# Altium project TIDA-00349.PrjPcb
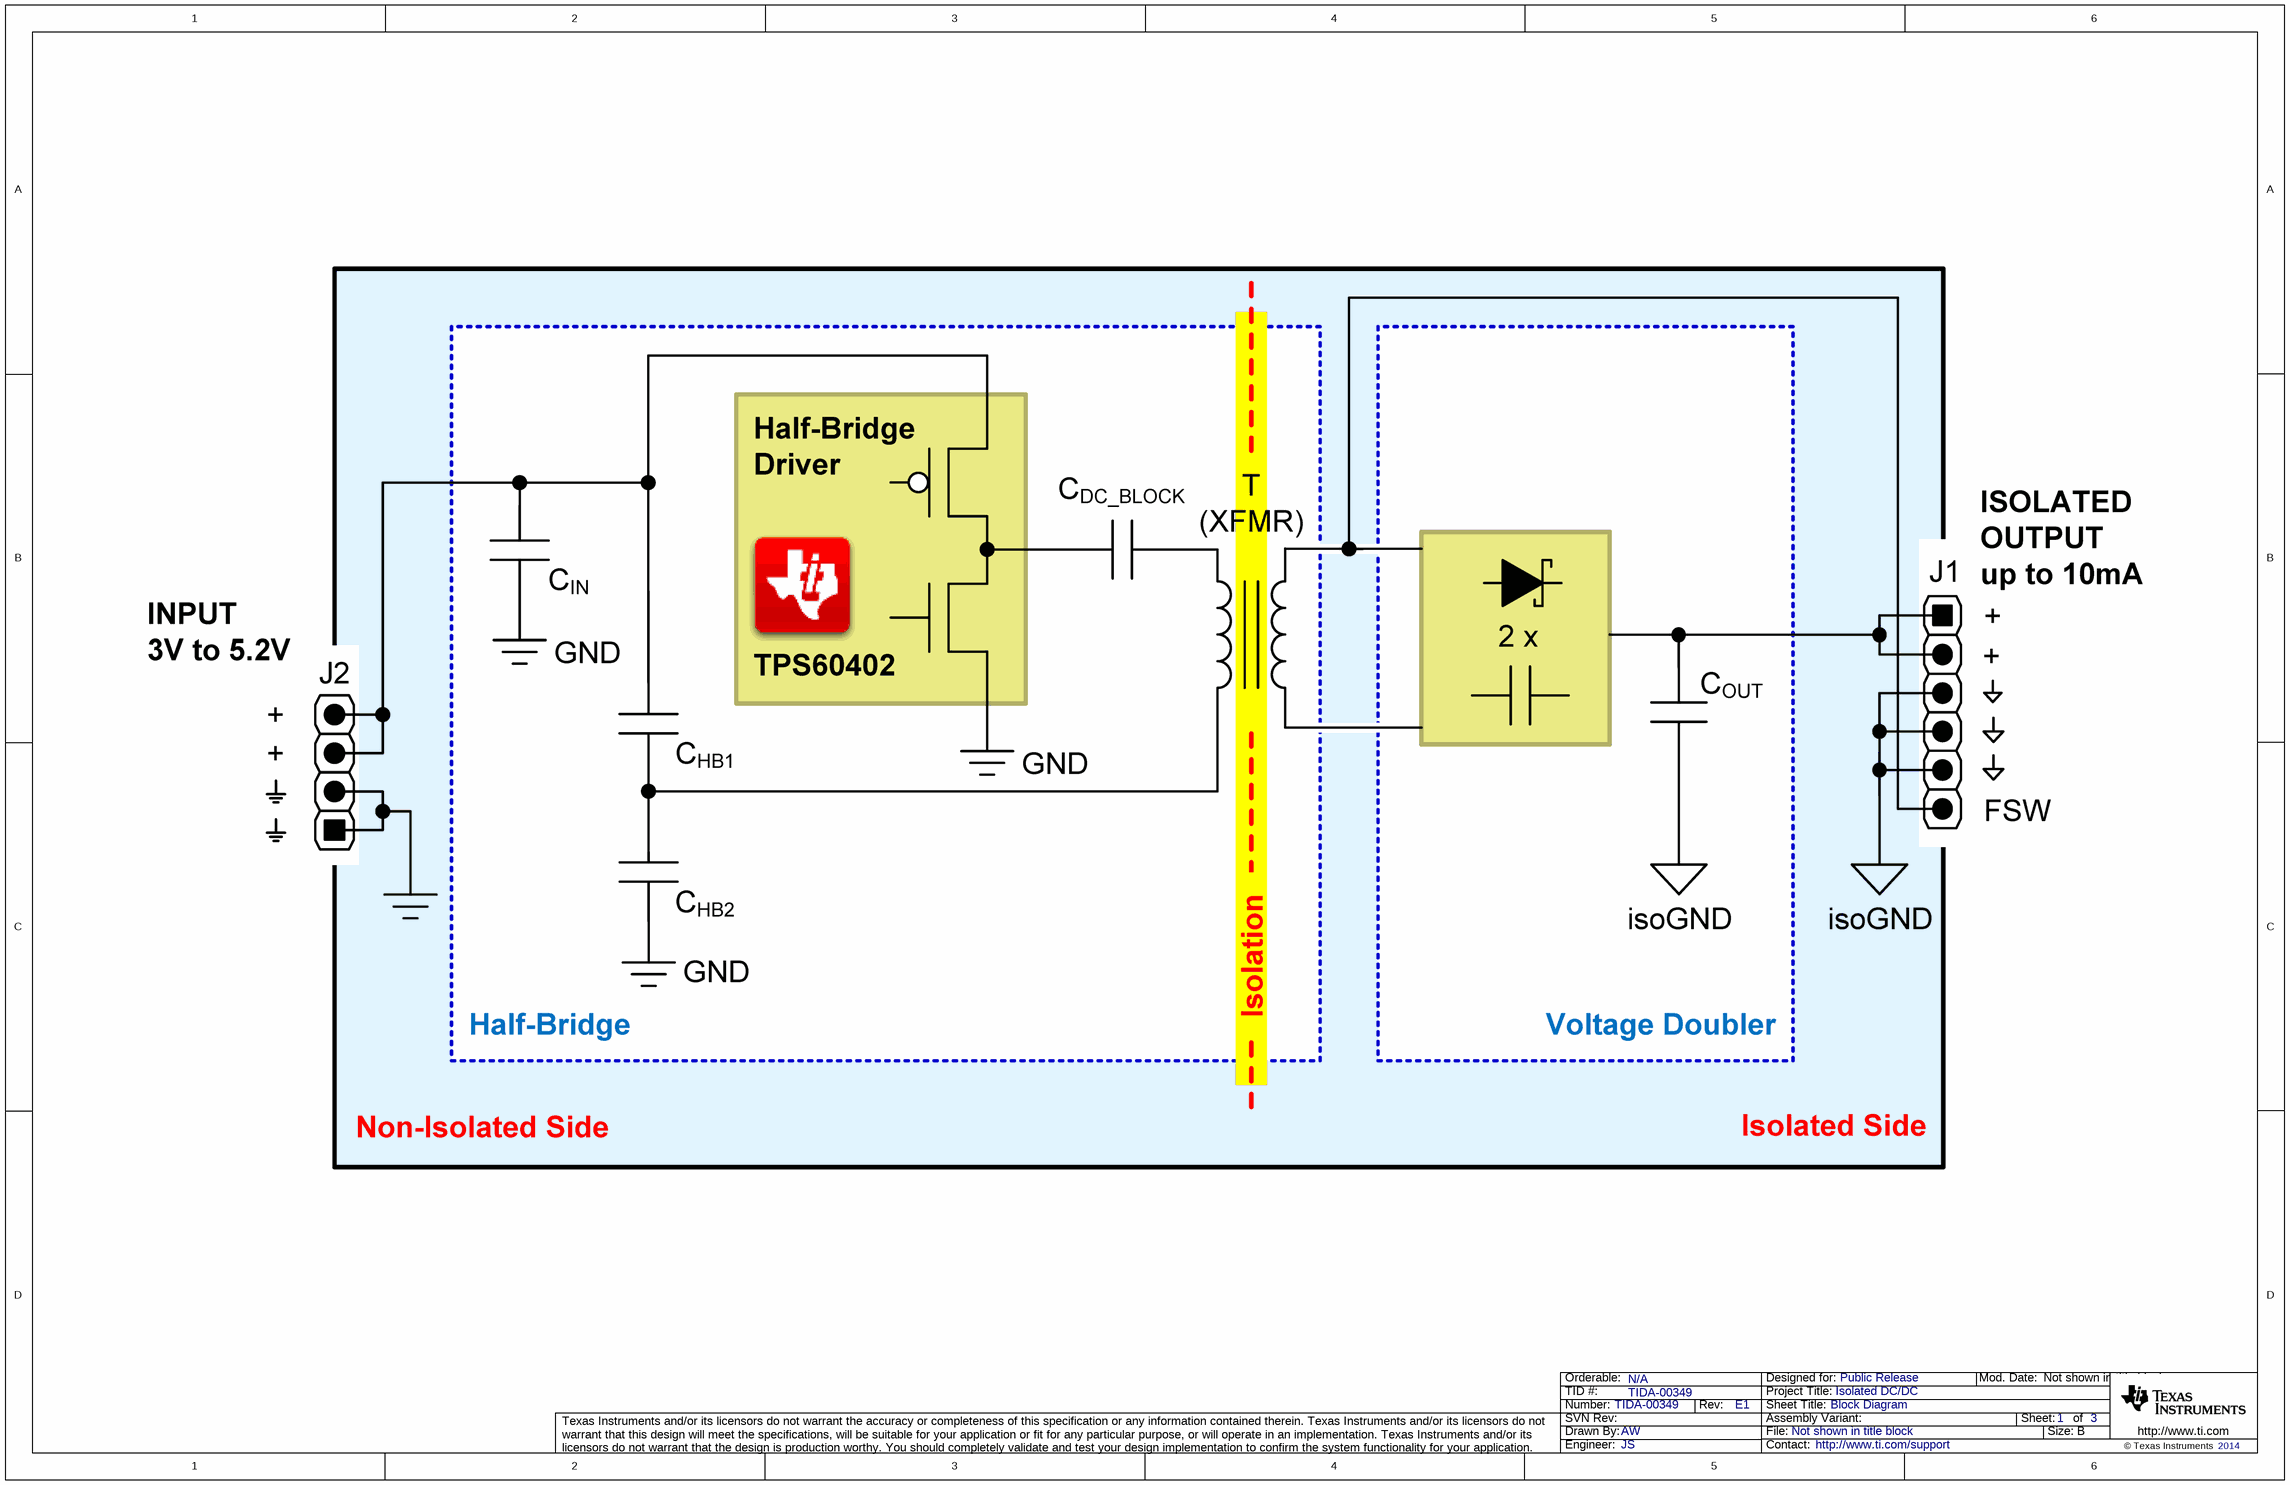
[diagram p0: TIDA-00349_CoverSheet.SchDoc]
CopyrightYear: 2014; EVM_Orderable: N/A; PCB_Layout: AW; PCB_Rev: E1; PRJ_Customer: Public Release; PRJ_Engineer: JS; PRJ_Number: TIDA-00349; PRJ_Title: Isolated DC/DC; SCH_Rev: E1; TechSupport: http://www.ti.com/support; TID: TIDA-00349
3 sheets, 49 parts. Net scope: global (net labels, ports and power ports of the same name join across sheets).
Board file: TIDA-00349_TID.PcbDoc
Sheets:
  TIDA-00349_CoverSheet.SchDoc
  TIDA-00349_IsolatedDCDC.SchDoc
  TIDA-00349_TID_Hardware.SchDoc

## Sheet TIDA-00349_CoverSheet.SchDoc: Block Diagram
size 431 x 279 mm; Date: Not shown in title block; ApprovedBy: Not shown in title block; CheckedBy: Not shown in title block; Author: Not shown in title block; CompanyName: Not shown in title block; DrawnBy: AW; Engineer: Not shown in title block; Organization: Not shown in title block; Address1: Not shown in title block; Address2: Not shown in title block; Address3: Not shown in title block; Address4: Not shown in title block; DocumentNumber: 1; Revision: Use project parameter SCH_Rev; SheetNumber: 1; SheetTotal: 3; PageSetup: Record=PageOptions¦CenterHorizontal=True¦CenterVertical=True¦PrintScale=1.00¦XCorrection=1.00¦YCorrection=1.00¦PrintKind=0¦BorderSize=5000000¦LeftOffset=0¦BottomOffset=0¦Orientation=2¦PaperLength=1000¦PaperWidth=1000¦Scale=100¦PaperSource=15¦PrintQuality=600¦MediaType=1¦DitherType=10¦PaperKind=Letter¦PrintScaleMode=1

## Sheet TIDA-00349_IsolatedDCDC.SchDoc: Isolated DC/DC Converter
size 431 x 279 mm; Date: Not shown in title block; ApprovedBy: Not shown in title block; CheckedBy: Not shown in title block; Author: Not shown in title block; CompanyName: Not shown in title block; DrawnBy: AW; Engineer: Not shown in title block; Organization: Not shown in title block; Address1: Not shown in title block; Address2: Not shown in title block; Address3: Not shown in title block; Address4: Not shown in title block; DocumentNumber: 2; Revision: Use project parameter SCH_Rev; SheetNumber: 2; SheetTotal: 3; PageSetup: Record=PageOptions¦CenterHorizontal=True¦CenterVertical=True¦PrintScale=0.94¦XCorrection=1.00¦YCorrection=1.00¦PrintKind=0¦BorderSize=5000000¦LeftOffset=0¦BottomOffset=0¦Orientation=2¦PaperLength=4200¦PaperWidth=2970¦Scale=100¦PaperSource=7¦PrintQuality=600¦MediaType=1¦DitherType=10¦PrintScaleMode=1¦PaperKind=A3¦PaperIndex=8
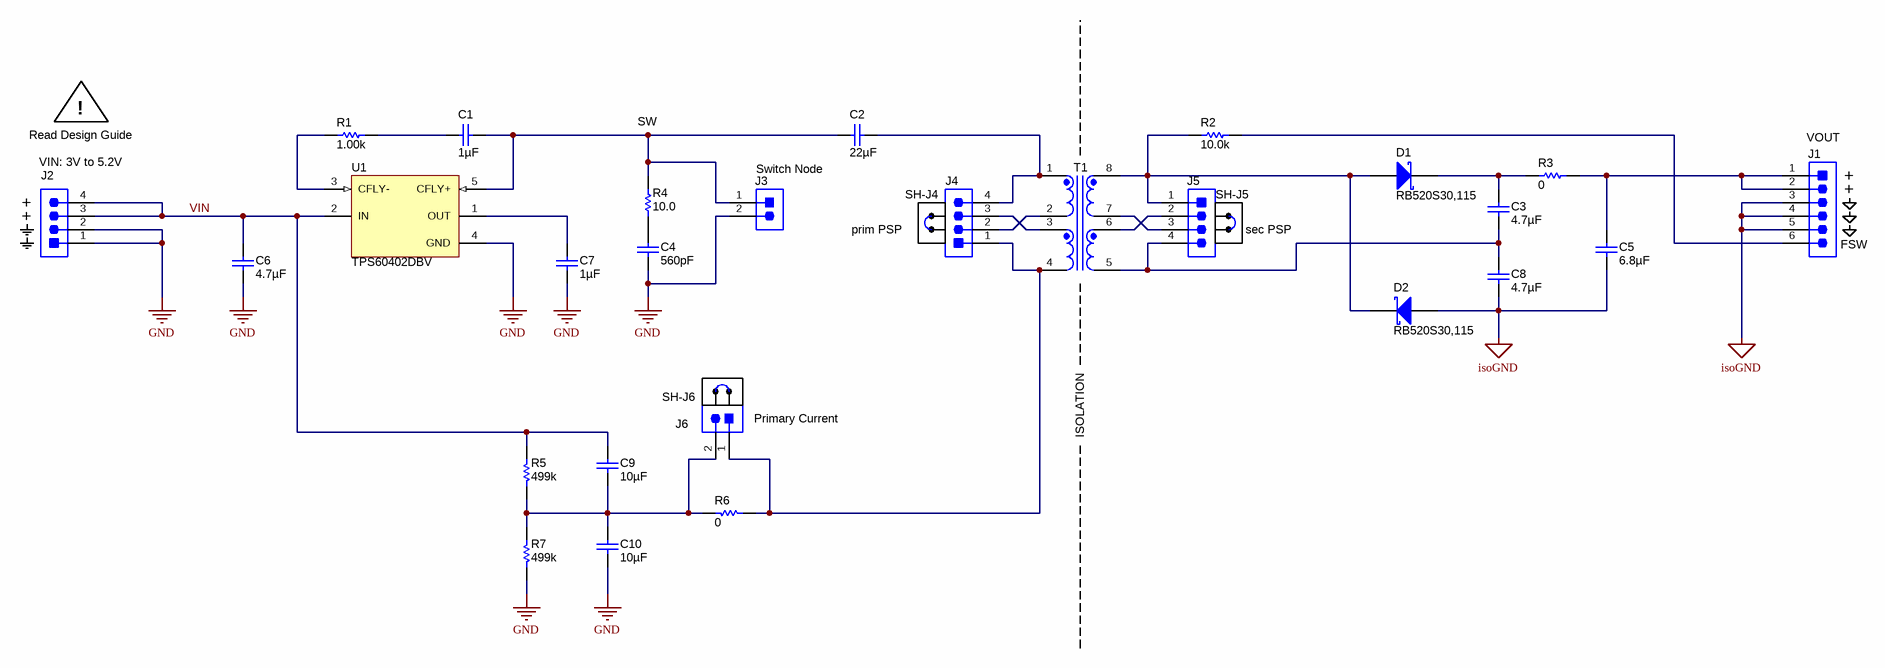
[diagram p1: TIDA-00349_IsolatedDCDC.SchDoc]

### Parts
C1  ValueDisplayed: 1µF  [0402S]  (hidden comment: CAP, CERM, 1uF, 10V, +/-10%, X5R, 0402)
C2  ValueDisplayed: 22µF  [1206]  (hidden comment: CAP, CERM, 22uF, 10V, +/-10%, X5R, 1206)
C3  ValueDisplayed: 4.7µF  [0603]  (hidden comment: CGB3B1X5R1A475K055AC)
C4  ValueDisplayed: 560pF  [0402]  (hidden comment: GRM155R71H561KA01D)
C5  ValueDisplayed: 6.8µF  [0603]  (hidden comment: C1608X5R1E685K080AC)
C6  ValueDisplayed: 4.7µF  [0603S]  (hidden comment: C0603C475K8PACTU)
C7  ValueDisplayed: 1µF  [0603S]  (hidden comment: GRM188R71A105KA61D)
C8  ValueDisplayed: 4.7µF  [0603]  (hidden comment: CGB3B1X5R1A475K055AC)
C9  ValueDisplayed: 10µF  [0805_HV]  (hidden comment: CAP, CERM, 10uF, 10V, +/-10%, X7R, 0805)
C10  ValueDisplayed: 10µF  [0805_HV]  (hidden comment: CAP, CERM, 10uF, 10V, +/-10%, X7R, 0805)
D1  RB520S30,115  [SOD-523]
D2  RB520S30,115  [SOD-523]
J1  61300611121  [WURTH_61300611121]  (value not drawn)
J2  61300411121  [WURTH_61300411121]  (value not drawn)
J3  61300211121  [WURTH_61300211121]  (value not drawn)
J4  61300411121  [WURTH_61300411121]  (value not drawn)
J5  61300411121  [WURTH_61300411121]  (value not drawn)
J6  61300211121  [WURTH_61300211121]  (value not drawn)
R1  value 1.00k  [0402S]  (hidden comment: RES, 1.00k ohm, 1%, 0.063W, 0402)
R2  ValueDisplayed: 10.0k  [0402]  (hidden comment: CRCW040210K0FKED)
R3  ValueDisplayed: 0  [0805_HV]  (hidden comment: CRCW08050000Z0EAHP)
R4  value 10.0  [0402]  (hidden comment: RES, 10.0 ohm, 1%, 0.063W, 0402)
R5  value 499k  [0402]  (hidden comment: RES, 499k ohm, 1%, 0.063W, 0402)
R6  ValueDisplayed: 0  [0805_HV]  (hidden comment: CRCW08050000Z0EAHP)
R7  value 499k  [0402]  (hidden comment: RES, 499k ohm, 1%, 0.063W, 0402)
SH-J4  969102-0000-DA  [SNT-100-BK-G]  (value not drawn)
SH-J5  969102-0000-DA  [SNT-100-BK-G]  (value not drawn)
SH-J6  969102-0000-DA  [SNT-100-BK-G]  (value not drawn)
T1  750314839  [Wurth_750314445]  (value not drawn)
U1  TPS60402DBV  [DBV0005A_N]

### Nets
GND: C4.2 C6.2 C7.2 C10.2 J2.1 J2.2 J3.2 R7.1 U1.4(GND)
isoGND: C5.2 C8.2 D2.2(A) J1.3 J1.4 J1.5
VIN: C6.1 C9.1 J2.3 J2.4 R5.2 U1.2(IN)
NetC1_1: C1.1 R1.2
NetC1_2: C1.2 C2.2 J3.1 R4.2 U1.5(CFLY+)
NetC2_1: C2.1 J4.4 T1.1
NetC3_1: C3.1 D1.1(K) R3.1
NetC3_2: C3.2 C8.1 J5.4 T1.5
NetC4_1: C4.1 R4.1
NetC5_1: C5.1 J1.1 J1.2 R3.2
NetC7_1: C7.1 U1.1(OUT)
NetC9_2: C9.2 C10.1 J6.2 R5.1 R6.2 R7.2
NetD1_2: D1.2(A) D2.1(K) J5.1 R2.1 T1.8
NetJ1_6: J1.6 R2.2
NetJ4_1: J4.1 J6.1 R6.1 T1.4
NetJ4_2: J4.2 T1.2
NetJ4_3: J4.3 T1.3
NetJ5_2: J5.2 T1.6
NetJ5_3: J5.3 T1.7
NetR1_1: R1.1 U1.3(CFLY-)

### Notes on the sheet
- !
- Read Design Guide
- SW
- (near J1) VOUT
- (near J2) +
- (near J2) VIN: 3V to 5.2V
- Switch Node
- (near J1) +
- (near SH-J4) prim PSP
- (near SH-J5) sec PSP
- (near J1) FSW
- (near J6) Primary Current
- ISOLATION

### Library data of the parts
C1 = GRM155R61A105KE15D: Manufacturer: MuRata; Polarized: N; CompType: Capacitor; U/M: EA; Cap_F: 0.000001; Tolerance_%: 10; Value1: Unknown; TaMin_C: -55; TaMax_C: 85; Cap_Case: 0402
C2 = GRM31CR61A226KE19L: Manufacturer: MuRata; Polarized: N; CompType: Capacitor; U/M: EA; Cap_F: 0.000022; Tolerance_%: 10; Value1: Unknown; TaMin_C: -55; TaMax_C: 85
C3 C8 = CGB3B1X5R1A475K055AC: CAP, CERM, 4.7 µF, 10 V, +/- 10%, X5R, 0603; Manufacturer: TDK; Polarized: N; CompType: Capacitor; Value: 4.7uF; U/M: EA; Cap_F: 0.0000047; Tolerance_%: 10; Value1: Unknown; Value2: 10V; TaMin_C: -55; TaMax_C: 85
C4 = GRM155R71H561KA01D: CAP, CERM, 560pF, 50V, +/-10%, X7R, 0402; Manufacturer: MuRata; Polarized: N; CompType: Capacitor; U/M: EA; Cap_F: 0.00000000056; Tolerance_%: 10; Value1: Unknown; VDC_V: 50; TaMin_C: -55; TaMax_C: 125
C5 = C1608X5R1E685K080AC: CAP, CERM, 6.8 µF, 25 V, +/- 10%, X5R, 0603; Manufacturer: TDK; Polarized: N; CompType: Capacitor; Value: 6.8uF; U/M: EA; Cap_F: 0.0000068; Tolerance_%: 10; Value1: Unknown; VDC_V: 25; Value2: 25V; TaMin_C: -55; TaMax_C: 85
C6 = C0603C475K8PACTU: CAP, CERM, 4.7uF, 10V, +/-10%, X5R, 0603; Manufacturer: Kemet; Polarized: N; CompType: Capacitor; U/M: EA; Cap_F: 0.0000047; Tolerance_%: 10; ESR_Ohm: 0.006; Value1: 0.006 ohm; IRMS_A: 7.24; TaMin_C: -55; TaMax_C: 85; Cap_Case: 0603
C7 = GRM188R71A105KA61D: CAP, CERM, 1uF, 10V, +/-10%, X7R, 0603; Manufacturer: MuRata; Polarized: N; CompType: Capacitor; U/M: EA; Cap_F: 0.000001; Tolerance_%: 10; ESR_Ohm: 0.011; Value1: 0.011 ohm; TaMin_C: -55; TaMax_C: 125; Cap_Case: 0603
C9 C10 = GRM21BR71A106KE51L: Manufacturer: MuRata; Polarized: N; CompType: Capacitor; U/M: EA; Cap_F: 0.00001; Tolerance_%: 10; ESR_Ohm: 0.003; Value1: 0.003 ohm; TaMin_C: -55; TaMax_C: 125; Cap_Case: 0805
D1 D2 = RB520S30,115: Diode, Schottky, 30 V, 0.2 A, SOD-523; Manufacturer: NXP Semiconductor; U/M: EA; Vf_V: 0.6; Value: 30V; Value1: 0.2A; Value2: 0.6V; Io_A: 0.2; Vr_V: 30; TJmax_C: 150
J1 = 61300611121: Header, 2.54 mm, 6x1, Gold, TH; Manufacturer: Wurth Elektronik eiSos; SymbolCreator: a0412235; U/M: EA
J2 J4 J5 = 61300411121: Header, 2.54 mm, 4x1, Gold, TH; Manufacturer: Wurth Elektronik eiSos; SymbolCreator: a0412235; U/M: EA
J3 J6 = 61300211121: Header, 2.54 mm, 2x1, Gold, TH; Manufacturer: Wurth Elektronik eiSos; SymbolCreator: a0412235; U/M: EA
R1 = CRCW04021K00FKED: Manufacturer: Vishay-Dale; CompType: Resistor; Res_ohm: 1000; Value_Code: 1k00; Tolerance_%: 1; Power_W: 0.063; VDC_V: 50; TempCo: 100 ppm/C; EIA_Code: E96; U/M: EA
R2 = CRCW040210K0FKED: RES, 10.0 k, 1%, 0.063 W, 0402; Manufacturer: Vishay-Dale; CompType: Resistor; Value: 10.0k; Res_ohm: 10000; Value_Code: 10k0; Tolerance_%: 1; Power_W: 0.063; Value2: 0.063W; VDC_V: 50; TempCo: 100 ppm/C; EIA_Code: E96; U/M: EA
R3 R6 = CRCW08050000Z0EAHP: RES, 0, 5%, 0.333 W, 0805; Manufacturer: Vishay-Dale; CompType: Resistor; Value: 0; Value_Code: 0000; Tolerance_%: 5; Power_W: 0.333; Value2: 0.333W; TempCo: 200 ppm/C; EIA_Code: E24; U/M: EA
R4 = CRCW040210R0FKED: Manufacturer: Vishay-Dale; CompType: Resistor; Res_ohm: 10; Value_Code: 10R0; Tolerance_%: 1; Power_W: 0.063; VDC_V: 50; TempCo: 100 ppm/C; EIA_Code: E96; U/M: EA
R5 R7 = CRCW0402499KFKED: Manufacturer: Vishay-Dale; CompType: Resistor; Res_ohm: 499000; Tolerance_%: 1; Power_W: 0.063; VDC_V: 50; TempCo: 100 ppm/C; EIA_Code: E96; U/M: EA
SH-J4-SH-J6 = 969102-0000-DA: Shunt, 100mil, Gold plated, Black; Manufacturer: 3M; Alternate Manufacturer: Samtec; Value: 1x2; Note: You can "mate" this to a header by matching the designator.  i.e. use SH-J3 for header J3
T1 = 750314839: Transformer, 3mH, SMT; Manufacturer: Wurth Elektronik eiSos; SymbolCreator: a0799628; DCR_Ohm: 1.2; U/M: EA
U1 = TPS60402DBV: UNREGULATED 60-mA CHARGE PUMP VOLTAGE INVERTER, DBV0005A; Alternate Manufacturer: None; Manufacturer: Texas Instruments; SymbolCreator: a0799628; CompType: IC; U/M: EA

## Sheet TIDA-00349_TID_Hardware.SchDoc
size 431 x 279 mm; Date: Not shown in title block; ApprovedBy: Not shown in title block; CheckedBy: Not shown in title block; Author: Not shown in title block; CompanyName: Not shown in title block; Engineer: Not shown in title block; Organization: Not shown in title block; Address1: Not shown in title block; Address2: Not shown in title block; Address3: Not shown in title block; Address4: Not shown in title block; DocumentNumber: 3; Revision: Use project parameter SCH_Rev; SheetNumber: 3; SheetTotal: 3; PageSetup: Record=PageOptions¦CenterHorizontal=True¦CenterVertical=True¦PrintScale=1.00¦XCorrection=1.00¦YCorrection=1.00¦PrintKind=0¦BorderSize=5000000¦LeftOffset=0¦BottomOffset=0¦Orientation=2¦PaperLength=1000¦PaperWidth=1000¦Scale=100¦PaperSource=15¦PrintQuality=600¦MediaType=1¦DitherType=10¦PaperKind=Letter¦PrintScaleMode=1
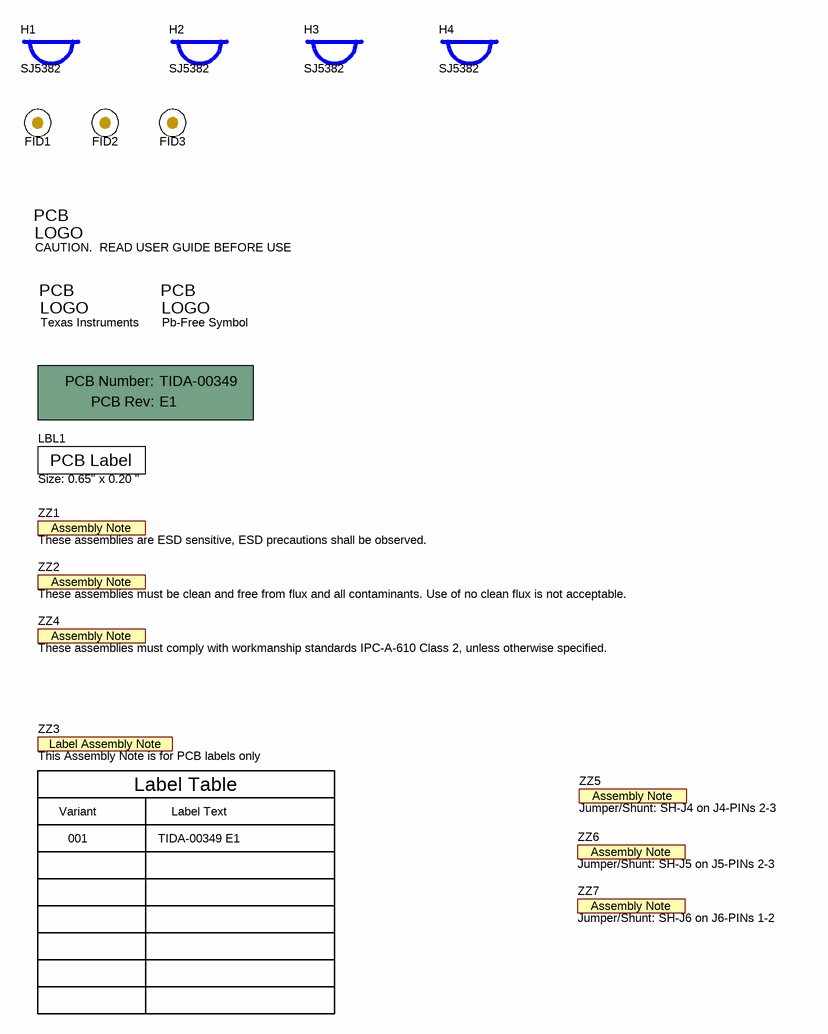
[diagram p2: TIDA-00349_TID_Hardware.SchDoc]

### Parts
!PCB1  Printed Circuit Board  (value not drawn)  (mechanical)
FID1  Fiducial  [Fiducial10-20]  (value not drawn)
FID2  Fiducial  [Fiducial10-20]  (value not drawn)
FID3  Fiducial  [Fiducial10-20]  (value not drawn)
H1  SJ5382  [3M_SJ5382]
H2  SJ5382  [3M_SJ5382]
H3  SJ5382  [3M_SJ5382]
H4  SJ5382  [3M_SJ5382]
LBL1  Size: 0.65" x 0.20 "  [Label_650x200]
Logo1  CAUTION.  READ USER GUIDE BEFORE USE  [IEC_Caution_Small]  (no BOM)
Logo2  Texas Instruments  [TI_Stacked_Overlay_Small_Vertical]  (no BOM)
Logo3  Pb-Free Symbol  [Pb-Free_Overlay_Small]  (no BOM)
ZZ1  These assemblies are ESD sensitive, ESD precautions shall be observed.  [AssemblyNote]  (no BOM)
ZZ2  These assemblies must be clean and free from flux and all contaminants. Use of no clean flux is not acceptable.  [AssemblyNote]  (no BOM)
ZZ3  This Assembly Note is for PCB labels only  [AssemblyNoteLabel]  (no BOM)
ZZ4  These assemblies must comply with workmanship standards IPC-A-610 Class 2, unless otherwise specified.  [AssemblyNote]  (no BOM)
ZZ5  Jumper/Shunt: SH-J4 on J4-PINs 2-3  [AssemblyNote]  (no BOM)
ZZ6  Jumper/Shunt: SH-J5 on J5-PINs 2-3  [AssemblyNote]  (no BOM)
ZZ7  Jumper/Shunt: SH-J6 on J6-PINs 1-2  [AssemblyNote]  (no BOM)

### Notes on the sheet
- (near ZZ3) Label Table
- Variant
- 001
- TIDA-00349 E1
- Label Text

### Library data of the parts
!PCB1 = PCB: Manufacturer: Any; PartNumber: TIDA-00349; SymbolCreator: a0412235
FID1-FID3 = Fiducial: Fiducial mark.  There is nothing to buy or mount.; SymbolCreator: codlsc
H1-H4 = SJ5382: Bumpon, Hemisphere, 0.25 X 0.075, Clear; Manufacturer: 3M; SymbolCreator: a0412235
LBL1 = THT-14-423-10: Thermal Transfer Printable Labels, 0.650" W x 0.200" H - 10,000 per roll; Manufacturer: Brady; SymbolCreator: a0412235; CompType: Label
Logo1 = IEC_Caution: IEC 61010-1 Caution Warning; SymbolCreator: a0412235
Logo2 = TI_Logo: Texas Instrument Corporate Signature; SymbolCreator: a0412235
Logo3 = Pb-Free: SymbolCreator: a0412235
ZZ1 ZZ2 ZZ4-ZZ7 = AssemblyNote: SymbolCreator: codlsc
ZZ3 = AssemblyNoteLabel: SymbolCreator: a0412235

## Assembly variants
001: not fitted C4 FID1 FID2 FID3 R4 R6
